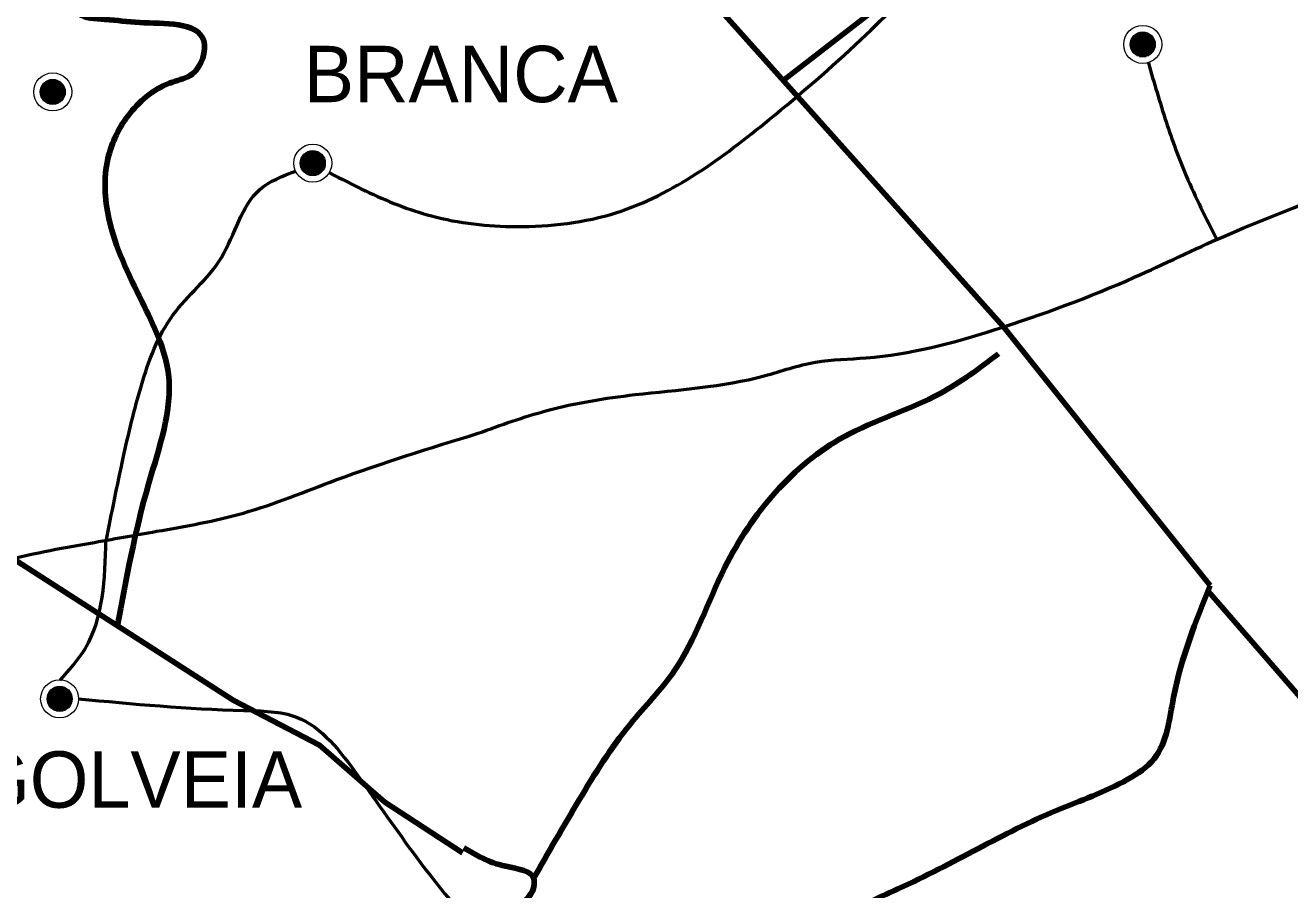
# Model space of a CAD drawing. Extents: x 512883 to 1063249, y 8784064 to 9081064.
# Drawn here: x 610987 to 644628, y 8955232 to 8978230 of the extents above; entities that cross this region are included whole.
import ezdxf

# ---------------------------------------------------------------- set-up
doc = ezdxf.new("R2010")
doc.units = 0
doc.header["$LTSCALE"] = 600
doc.linetypes.add('DOT_DASHED', pattern=[7.7, 5, -1.2, 0.3, -1.2])
doc.linetypes.add('MEDIUM_DASHED', pattern=[4.5, 3, -1.5])
for name, color, linetype, lineweight in [('10', 7, 'Continuous', 53), ('13', 7, 'Continuous', 90), ('4', 7, 'Continuous', 13), ('5', 7, 'Continuous', 13)]:
    doc.layers.add(name, color=color, linetype=linetype, lineweight=lineweight)

msp = doc.modelspace()

# ---------------------------------------------------------------- linework, layer by layer
at = {"layer": '10'}
for points in [[(623035.1, 8967374.9), (624860, 8967979.1), (627209.4, 8968402.5), (630649.8, 8968904.2), (632009.4, 8969267.8), (633363.5, 8969381.5), (636789.3, 8970133.6), (640491.3, 8971525.2), (642875.4, 8972614.8), (647070.4, 8974411.5), (649255.2, 8975610), (652066.3, 8976856.1), (655223.5, 8978239.8), (657993, 8979424.4), (660825.7, 8980732.5), (663131.9, 8981949), (665821.2, 8983156.3), (669257.4, 8984387.5), (671785.8, 8985619.5), (674003.2, 8986462.9), (676976.1, 8987726), (679604.9, 8988934.7), (682046.3, 8989877), (685063.7, 8991326.6), (686527.2, 8991833.7), (687385.5, 8992334.3), (687835.9, 8992636.2)], [(619078.8, 8974308), (620041, 8973823.3), (621792.4, 8973156.8), (624051.5, 8972874.9), (626723.8, 8973249.1), (630778, 8975720.1), (633214.7, 8977847.6), (635194.6, 8980000.8), (636549.7, 8982155.1), (637682.1, 8983973.8), (639103.6, 8986537.1), (640042.7, 8988767.2), (640878.1, 8990028.8)], [(640867.2, 8977227), (641341.1, 8975660.4), (641874.1, 8974225), (642686.4, 8972533.2)], [(613137.5, 8964498.8), (613593.7, 8966723), (614076, 8968645.5), (614913.6, 8970516.7), (616208.1, 8972054.6), (617224.4, 8973860), (618183.6, 8974350.7)], [(589369.3, 8956652.4), (591069.7, 8957841.5), (592953.4, 8959109.7), (595209.7, 8959889.7), (597460.5, 8960419.7), (599836, 8961113.4), (602622, 8962130.8), (605320.5, 8962837.8), (607526.5, 8963160.4), (610287.3, 8963949.2), (612719.2, 8964454), (614481.1, 8964766.4), (616791.5, 8965253.3), (619251.8, 8966132.6), (623035.1, 8967374.9)], [(611913.2, 8960805.1), (612577.1, 8961643.8), (613134.4, 8964529.4)], [(612407.3, 8960309.6), (616797.8, 8960001.1), (618206, 8959821.7), (619826.6, 8958282.6), (621392.8, 8956098.7), (623537.3, 8953609.2), (626036.4, 8951653.2), (628092.4, 8949728.5), (628310.2, 8948618.7), (628567.2, 8946528.5), (628932.5, 8945707), (630296.3, 8945341.1), (631592.5, 8943726.3), (632545.4, 8942098.8), (634115.1, 8940998.5), (635163.6, 8940973.6), (636735.4, 8940894.5), (637165.8, 8940279.9), (637057, 8938073.3), (636977.6, 8936282.8), (637159.6, 8935382.3), (637714.6, 8934931.4), (637914.4, 8934843.3)]]:
    msp.add_spline(points, degree=3, dxfattribs=at)
at = {"layer": '13'}
msp.add_line((642459.7, 8963171), (648586.7, 8956097.6), dxfattribs=at)
for points in [[(642511.1, 8963328.2), (637014.7, 8970206.3), (616806.6, 8992811.6)], [(631154.6, 8976761.5), (636007.8, 8980531.2), (644880.2, 8982195.7), (648190.1, 8988723.7), (649329.8, 8985487), (651670.5, 8976281.9), (653317.6, 8975640.4)], [(594605.2, 8974358.7), (616521.5, 8960278.6), (618815.2, 8959077.8), (620557.2, 8957556.6), (622622.7, 8956208.8)]]:
    msp.add_lwpolyline(points, dxfattribs=at)
at = {"layer": '13', "lineweight": 25}
msp.add_spline([(683199.8, 8995975.2), (680498, 8997935.8), (679043.2, 8999679.4), (677914.4, 9000644.2), (677650.4, 9001484.1), (677080.2, 9002164.6), (675208.7, 9002375.9), (673140.1, 9002800.2), (672045.2, 9003472.4), (671974.6, 9003932.6), (670687.8, 9004129.9), (669347.8, 9004662), (667777.7, 9005741.4), (666333.1, 9007026.3), (665102.5, 9007951.8), (663816.7, 9008190.8), (662927.2, 9008107.7), (662967.1, 9008085.9), (661700, 9008262), (660081.2, 9007112.6), (657475.6, 9006966.1), (655519.4, 9006074.8), (653297.7, 9004970.1), (651116.9, 9003529.2), (648710.5, 9004673.8), (648047, 9004772.9), (646803.8, 9004198.1), (645340.7, 9003711.9), (645429.4, 9005002), (643752.2, 9004875.2), (643232.1, 9005075.1), (643032.7, 9005184.1), (643168.7, 9005868.6), (643726.2, 9007376.7), (644534.9, 9008378.7), (644346.9, 9009008.4), (643998.1, 9012434.7), (642265.5, 9015310.3), (641550.4, 9016744.6), (640911, 9017947.8), (640596.9, 9019268.2), (639994.6, 9020324.6), (638886.9, 9021330.5), (637357.8, 9020595.8), (635113.9, 9019461.2), (632349.6, 9017588.8), (631131.3, 9016304.8), (631387.2, 9015089.9), (630940.2, 9013099.8), (630844.7, 9011497.2), (630459.6, 9009568.2), (629405.6, 9006571.3), (628020.2, 9004461.8), (625763.8, 9002640.7), (625763.8, 9000819.6), (625836.6, 8999654.1), (625472.7, 8999435.5), (624380.9, 8999872.6), (623216.3, 8999581.2), (622051.7, 8999144.2), (619649.8, 8995939), (616883.9, 8992806.8), (615573.8, 8990548.6), (613899.7, 8987853.4), (613171.8, 8987197.8), (611206.6, 8986906.4), (609168.6, 8986032.3), (607640.1, 8986032.3), (605238.1, 8984794), (603345.7, 8984794), (602690.6, 8984721.1), (601016.5, 8983045.7), (597668.4, 8979913.4), (595557.6, 8977728.1), (594375.2, 8975355.1)], degree=3, dxfattribs=at)
at = {"layer": '13', "linetype": 'MEDIUM_DASHED', "lineweight": 70}
msp.add_spline([(683108.2, 8995958.5), (680406.4, 8997919.1), (678951.7, 8999662.7), (677822.9, 9000627.5), (677558.8, 9001467.4), (676988.7, 9002147.9), (675117.1, 9002359.2), (673048.5, 9002783.5), (671953.7, 9003455.7), (671883, 9003915.8), (670596.2, 9004113.2), (669256.2, 9004645.3), (667686.1, 9005724.7), (666241.5, 9007009.6), (665011, 9007935), (663725.1, 9008174.1), (662835.7, 9008091), (662875.5, 9008069.2), (661608.5, 9008245.3), (659989.6, 9007095.8), (657384, 9006949.4), (655427.9, 9006058.1), (653206.1, 9004953.4), (651025.3, 9003512.5), (648619, 9004657.1), (647955.4, 9004756.2), (646712.3, 9004181.4), (645249.2, 9003695.2), (645337.9, 9004985.2), (643660.7, 9004858.4), (643140.6, 9005058.4), (642941.2, 9005167.3), (643077.2, 9005851.9), (643634.7, 9007360), (644443.3, 9008362), (644255.3, 9008991.7), (643906.6, 9012418), (642174, 9015293.6), (641458.9, 9016727.9), (640819.5, 9017931), (640505.4, 9019251.5), (639903.1, 9020307.9), (638795.3, 9021313.8), (637266.3, 9020579.1), (635022.4, 9019444.5), (632258, 9017572.1), (631039.8, 9016288.1), (631295.6, 9015073.2), (630848.7, 9013083.1), (630753.1, 9011480.5), (630368, 9009551.5), (629314, 9006554.6), (627928.6, 9004445.1), (625672.3, 9002624), (625672.3, 9000802.9), (625745.1, 8999637.4), (625381.1, 8999418.8), (624289.3, 8999855.9), (623124.8, 8999564.5), (621960.2, 8999127.5), (619558.2, 8995922.3), (616792.4, 8992790.1), (615482.2, 8990531.9), (613808.1, 8987836.7), (613080.3, 8987181.1), (611115.1, 8986889.7), (609077, 8986015.6), (607548.5, 8986015.6), (605146.6, 8984777.2), (603254.2, 8984777.2), (602599.1, 8984704.4), (600925, 8983029), (597576.8, 8979896.7), (595466.1, 8977711.4), (594283.6, 8975338.4)], degree=3, dxfattribs=at)
at = {"layer": '13'}
for points in [[(613442.7, 8962256.6), (614266.5, 8966022), (614794.4, 8968948.1), (614090.2, 8970882.2), (613210.6, 8973091.5), (613184.7, 8974676), (613776.1, 8975891.6), (614903.7, 8976719.3), (615433, 8976935.9), (615734.8, 8977824.9), (614030.5, 8978303.1), (613104.4, 8978387.7), (612421.6, 8978529), (612589.1, 8979733.8), (613027.7, 8982266), (613522.9, 8983692.3), (614081.7, 8985262.9), (613838.7, 8986144), (613210.8, 8987251.6)], [(624494.5, 8955500), (625723, 8957621.2), (627078.2, 8959631.4), (628259.4, 8961062.2), (629602.3, 8963810.6), (632782.1, 8967290.6), (635323.8, 8968433.5), (636876, 8969485.5)], [(628390.4, 8938001.8), (629593, 8940752.8), (631557, 8941656.4), (632813.5, 8942363.4), (632468.5, 8945039.3), (632892.7, 8945987.9), (634417.1, 8947431.3), (634543.8, 8948616.3), (634014.8, 8950254.5), (632926.6, 8952156.1), (632502.4, 8953979.4), (632670.1, 8954267.2), (634204.7, 8955251.9), (638426.2, 8957339.8), (640320.5, 8958170), (641018.3, 8958716.1), (641538.2, 8960350.2), (642511.1, 8963328.2)], [(622657.3, 8956344.6), (623767.9, 8955854.6), (624526.4, 8955482.2), (624523.7, 8955357.2), (623455.6, 8954486.5), (622367.4, 8953616.2), (622231.4, 8952931.7), (621821.4, 8951711.8), (621762.9, 8950879.5), (622166.8, 8949973.7), (622198.6, 8948660), (622176.7, 8947660.1), (621863.9, 8946271.2), (621831, 8945688.4), (622022.6, 8945225.3), (622327, 8944384.4), (622380.2, 8944049.7), (622393.6, 8943736.8), (622313.1, 8942821.7), (621951.6, 8941776.5)]]:
    msp.add_spline(points, degree=3, dxfattribs=at)
at = {"layer": '4', "linetype": 'DOT_DASHED', "lineweight": 25}
msp.add_spline([(594265.9, 8975329.4), (594758.2, 8976156.6), (595328.6, 8977331), (596058, 8978397.4), (598038.2, 8980392.7), (599624.9, 8981918.1), (601578.2, 8983601.4), (602467, 8984580.6), (605014.9, 8984853.5), (606318.5, 8985426.8), (608090.4, 8986197.5), (609806.1, 8986240), (611475.9, 8986950.6), (613099.4, 8987391.3), (614128, 8988304.7), (615031.5, 8989950.5), (615962.3, 8991929.1), (617097.7, 8993110.8), (618138.6, 8994586.7), (619495.3, 8995742.3), (620495.5, 8997198.2), (621820.1, 8998729.8), (623389, 8999442.8), (624300.4, 8999608.7), (625491.4, 8999642.8), (625486.6, 9001268.6), (625379.3, 9001896.4), (626275, 9003188.1), (628271.3, 9004995.4), (628905.8, 9006335), (629717.5, 9008399.8), (630406.8, 9010405), (630770.1, 9011334.2), (630694.8, 9012503.2), (630652.5, 9013337.8), (631400.5, 9015258.2), (631064, 9016475.1), (631604.2, 9017191.7), (632870.7, 9017911.8), (634506.9, 9018935.8), (634961, 9019404.3), (636304, 9019935.1), (637932.1, 9020584.1), (638608, 9021047.3), (639161, 9021430.2), (640500.4, 9021794.3), (640952.2, 9022158.7), (641647.8, 9022600.6), (642829.6, 9022218.2), (643187.6, 9021980.4), (643666, 9021718.9)], degree=3, dxfattribs=at)
at = {"layer": '5'}
for p, q in [((640536.8, 8978000.4), (640899.2, 8978000.4)), ((640594.1, 8978030.4), (640841.9, 8978030.4)), ((640385.6, 8977730.4), (641050.4, 8977730.4)), ((640386.2, 8977700.4), (641050.1, 8977700.4)), ((640387.7, 8977760.4), (641048.3, 8977760.4)), ((640389.2, 8977670.4), (641046.8, 8977670.4)), ((640392.5, 8977790.4), (641043.5, 8977790.4)), ((640400.6, 8977820.4), (641035.4, 8977820.4)), ((640411.4, 8977850.4), (641024.6, 8977850.7)), ((640425.8, 8977880.4), (641010.5, 8977880.4)), ((640444.1, 8977910.4), (640992.2, 8977910.4)), ((640468.1, 8977940.4), (640968.5, 8977940.4)), ((640497.2, 8977970.4), (640938.8, 8977970.4)), ((640395.2, 8977640.4), (641040.8, 8977640.4)), ((640404.2, 8977610.4), (641031.8, 8977610.4)), ((640416.8, 8977580.4), (641019.5, 8977580.7)), ((640432.7, 8977550.4), (641003.3, 8977550.4)), ((640453.4, 8977520.4), (640982.9, 8977520.7)), ((640478.6, 8977490.1), (640957.7, 8977490.4)), ((640511.9, 8977460.4), (640924.1, 8977460.4)), ((640556.9, 8977430.4), (640879.1, 8977430.4)), ((640630.7, 8977400.4), (640805, 8977400.4)), ((611468, 8976676.7), (611968.4, 8976676.7)), ((611497.1, 8976706.7), (611938.7, 8976706.7)), ((611536.7, 8976736.7), (611899.1, 8976736.7)), ((611594, 8976766.7), (611841.8, 8976766.7)), ((611385.5, 8976466.7), (612050.3, 8976466.7)), ((611386.1, 8976436.7), (612050, 8976436.7)), ((611387.6, 8976496.7), (612048.2, 8976496.7)), ((611389.1, 8976406.7), (612046.7, 8976406.7)), ((611392.4, 8976526.7), (612043.4, 8976526.7)), ((611395.1, 8976376.7), (612040.7, 8976376.7)), ((611400.5, 8976556.7), (612035.3, 8976556.7)), ((611404.1, 8976346.7), (612031.7, 8976346.7)), ((611411.3, 8976586.7), (612024.5, 8976587)), ((611416.7, 8976316.7), (612019.4, 8976317)), ((611425.7, 8976616.7), (612010.4, 8976616.7)), ((611444, 8976646.7), (611992.1, 8976646.7)), ((611432.6, 8976286.7), (612003.2, 8976286.7)), ((611453.3, 8976256.7), (611982.8, 8976257)), ((611478.5, 8976226.4), (611957.6, 8976226.7)), ((611511.8, 8976196.7), (611924, 8976196.7)), ((611556.8, 8976166.7), (611879, 8976166.7)), ((611630.6, 8976136.7), (611804.9, 8976136.7)), ((618319.2, 8974661), (618954, 8974661)), ((618330, 8974691), (618943.2, 8974691.3)), ((618344.4, 8974721), (618929.1, 8974721)), ((618362.7, 8974751), (618910.8, 8974751)), ((618386.7, 8974781), (618887.1, 8974781)), ((618415.8, 8974811), (618857.4, 8974811)), ((618455.4, 8974841), (618817.8, 8974841)), ((618512.7, 8974871), (618760.5, 8974871)), ((618304.2, 8974571), (618969, 8974571)), ((618304.8, 8974541), (618968.7, 8974541)), ((618306.3, 8974601), (618966.9, 8974601)), ((618307.8, 8974511), (618965.4, 8974511)), ((618311.1, 8974631), (618962.1, 8974631)), ((618313.8, 8974481), (618959.4, 8974481)), ((618322.8, 8974451), (618950.4, 8974451)), ((618335.4, 8974421), (618938.1, 8974421.3)), ((618351.3, 8974391), (618921.9, 8974391)), ((618372, 8974361), (618901.5, 8974361.3)), ((618397.2, 8974330.7), (618876.3, 8974331)), ((618430.5, 8974301), (618842.7, 8974301)), ((618475.5, 8974271), (618797.7, 8974271)), ((618549.3, 8974241), (618723.6, 8974241)), ((611651.3, 8960528.6), (612151.7, 8960528.6)), ((611680.4, 8960558.6), (612122, 8960558.6)), ((611720, 8960588.6), (612082.4, 8960588.6)), ((611777.3, 8960618.6), (612025.1, 8960618.6)), ((611568.8, 8960318.6), (612233.6, 8960318.6)), ((611569.4, 8960288.6), (612233.3, 8960288.6)), ((611570.9, 8960348.6), (612231.5, 8960348.6)), ((611572.4, 8960258.6), (612230, 8960258.6)), ((611575.7, 8960378.6), (612226.7, 8960378.6)), ((611578.4, 8960228.6), (612224, 8960228.6)), ((611583.8, 8960408.6), (612218.6, 8960408.6)), ((611587.4, 8960198.6), (612215, 8960198.6)), ((611594.6, 8960438.6), (612207.8, 8960438.9)), ((611600, 8960168.6), (612202.7, 8960168.9)), ((611609, 8960468.6), (612193.7, 8960468.6)), ((611627.3, 8960498.6), (612175.4, 8960498.6)), ((611615.9, 8960138.6), (612186.5, 8960138.6)), ((611636.6, 8960108.6), (612166.1, 8960108.9)), ((611661.8, 8960078.3), (612140.9, 8960078.6)), ((611695.1, 8960048.6), (612107.3, 8960048.6)), ((611740.1, 8960018.6), (612062.3, 8960018.6)), ((611813.9, 8959988.6), (611988.2, 8959988.6))]:
    msp.add_line(p, q, dxfattribs=at)
for centre, radius in [((640718.1, 8977721.4), 506.1), ((640718.1, 8977721.4), 332.9), ((611718, 8976457.7), 506.1), ((611718, 8976457.7), 332.9), ((618636.7, 8974562), 506.1), ((618636.7, 8974562), 332.9), ((611901.2, 8960309.6), 506.1), ((611901.2, 8960309.6), 332.9)]:
    msp.add_circle(centre, radius, dxfattribs=at)

# ---------------------------------------------------------------- texts
for s, p in [('BRANCA', (618396.1, 8976183.8)), ('DELMIRO GOLVEIA', (599850.9, 8957412.6))]:
    msp.add_text(s, height=1500, dxfattribs=at).set_placement(p)

doc.saveas('drawing.dxf')
